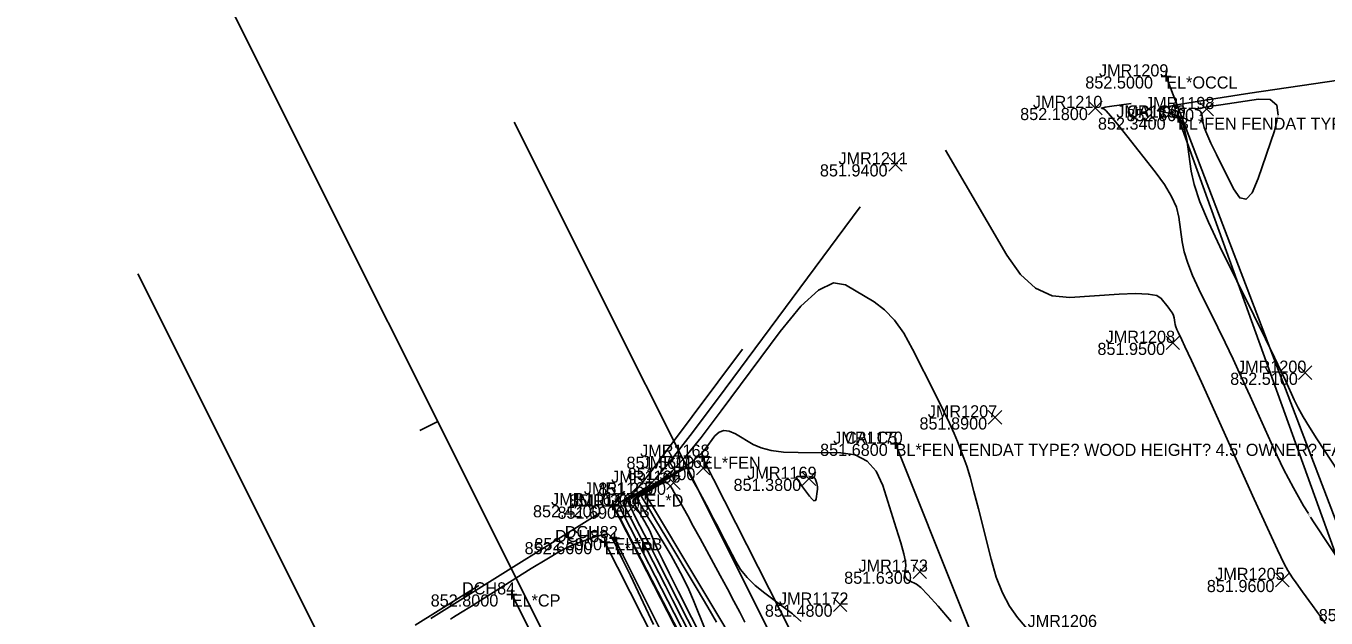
# Model space of a CAD drawing. Extents: x 1654928 to 1810050, y 486881 to 626330.
# Drawn here: x 1801297.5 to 1801426.1, y 489990.4 to 490049 of the extents above; entities that cross this region are included whole.
import ezdxf

# ---------------------------------------------------------------- set-up
doc = ezdxf.new("R2010")
doc.units = 0
for name, color, linetype in [('DR_X_Ditch', 7, 'Continuous'), ('DT_X_Contour_Major', 7, 'Continuous'), ('DT_X_Contour_Minor', 7, 'Continuous'), ('PV_X_EOP', 7, 'Continuous'), ('PV_X_Shoulder', 7, 'Continuous'), ('RD_X_Fence', 7, 'Continuous'), ('RW_X_Esmt_SH', 7, 'Continuous'), ('SV_X_Break_Lines', 7, 'Continuous'), ('SV_X_Center_of_Pavt', 7, 'Continuous'), ('SV_X_CL_Survey_20', 7, 'Continuous'), ('SV_X_Occupation_Line', 7, 'Continuous'), ('SV_X_Random_Point', 7, 'Continuous'), ('SV_X_Shot_Marker', 7, 'Continuous'), ('SV_X_Text_Comment', 7, 'Continuous'), ('SV_X_Text_Elevation', 7, 'Continuous'), ('SV_X_Text_Name', 7, 'Continuous')]:
    doc.layers.add(name, color=color, linetype=linetype)

msp = doc.modelspace()

# ---------------------------------------------------------------- linework, layer by layer
at = {"layer": 'DR_X_Ditch'}
msp.add_lwpolyline([(1801398.42, 489926.9), (1801390.07, 489943.2), (1801378.94, 489964.4), (1801369.21, 489985.15), (1801358.75, 490002.61)], dxfattribs=at)
at = {"layer": 'DT_X_Contour_Major'}
for points in [[(1801388.41, 490036.67), (1801394.48, 490026.3), (1801395.85, 490024.36), (1801397.34, 490023.02), (1801398.97, 490022.26), (1801400.73, 490022.09), (1801405.6, 490022.42), (1801407.23, 490022.48), (1801408.47, 490022.44), (1801409.31, 490022.28), (1801409.77, 490022), (1801410.46, 490021.13), (1801410.69, 490020.82), (1801410.87, 490020.54), (1801410.98, 490020.3), (1801411.03, 490020.1), (1801411.1, 490019.61), (1801411.14, 490019.41), (1801411.21, 490019.19), (1801411.31, 490018.94), (1801411.43, 490018.67), (1801411.81, 490017.91), (1801412.11, 490017.26), (1801412.75, 490015.86), (1801413.73, 490013.72), (1801418.97, 490002.14), (1801420.28, 489999.26), (1801421.27, 489997.12), (1801421.93, 489995.73), (1801422.28, 489995.08), (1801422.76, 489994.35), (1801423.1, 489993.86), (1801423.75, 489992.95), (1801424.73, 489991.61), (1801426.02, 489989.84)], [(1801379.98, 490031.06), (1801365.87, 490012.04), (1801363.16, 490008.43), (1801361.08, 490005.77), (1801359.64, 490004.05), (1801358.82, 490003.27), (1801357.49, 490002.46), (1801357.05, 490002.19), (1801356.75, 490001.98), (1801356.58, 490001.83), (1801356.54, 490001.74), (1801356.61, 490001.58), (1801356.71, 490001.38), (1801357.33, 490000.16), (1801360.06, 489994.86), (1801360.72, 489993.56), (1801361.43, 489992.17), (1801364.25, 489986.6)]]:
    msp.add_lwpolyline(points, dxfattribs=at)
at = {"layer": 'DT_X_Contour_Minor'}
for points in [[(1801442.36, 490045.83), (1801418.51, 490042.31), (1801414.11, 490041.64), (1801411.12, 490041.13), (1801409.55, 490040.78), (1801409.39, 490040.58), (1801410.86, 490040.29), (1801411.36, 490040.05), (1801411.76, 490039.54), (1801412.07, 490038.77), (1801412.28, 490037.73), (1801412.71, 490034.61), (1801413.01, 490033.27), (1801413.59, 490031.58), (1801414.43, 490029.54), (1801415.56, 490027.16), (1801418.92, 490020.35), (1801420.06, 490018.02), (1801420.96, 490016.16), (1801421.63, 490014.76), (1801422.07, 490013.83), (1801422.92, 490011.96), (1801423.3, 490011.19), (1801423.8, 490010.29), (1801424.42, 490009.26), (1801425.16, 490008.11), (1801427.3, 490004.85)], [(1801424.32, 490000.73), (1801423.84, 490001.48), (1801422.83, 490003.26), (1801421.86, 490005.11), (1801420.94, 490007.05), (1801418.55, 490012.33), (1801417.68, 490014.24), (1801416.86, 490016.01), (1801416.08, 490017.64), (1801415.36, 490019.13), (1801413.49, 490022.92), (1801412.87, 490024.27), (1801412.38, 490025.51), (1801412.04, 490026.62), (1801411.84, 490027.6), (1801411.5, 490030.06), (1801411.26, 490031.03), (1801410.78, 490032.11), (1801410.08, 490033.28), (1801409.15, 490034.55), (1801406.36, 490038.09), (1801405.43, 490039.25), (1801404.74, 490040.08), (1801404.3, 490040.59), (1801404.09, 490040.77), (1801403.87, 490040.82), (1801403.85, 490040.84), (1801403.97, 490040.88), (1801404.23, 490040.93), (1801404.63, 490040.99), (1801406.8, 490041.31)], [(1801415.23, 490036.25), (1801414.68, 490037.39), (1801414.27, 490038.29), (1801414.01, 490038.94), (1801413.9, 490039.33), (1801413.8, 490040.05), (1801413.76, 490040.29), (1801413.68, 490040.47), (1801413.59, 490040.59), (1801413.48, 490040.64), (1801413.14, 490040.71), (1801413.2, 490040.76), (1801413.64, 490040.85), (1801414.47, 490040.99), (1801415.67, 490041.17), (1801419.39, 490041.72), (1801420.53, 490041.68), (1801421.18, 490041.14), (1801421.32, 490040.14)], [(1801421.23, 490039.73), (1801420.97, 490038.58), (1801419.36, 490033.86), (1801418.76, 490032.46), (1801418.15, 490031.83), (1801417.53, 490031.96), (1801416.9, 490032.85), (1801415.23, 490036.25)], [(1801397.82, 489987.74), (1801395.56, 489990.43), (1801394.76, 489991.54), (1801394.06, 489992.88), (1801393.45, 489994.43), (1801392.93, 489996.19), (1801391.68, 490001.19), (1801391.24, 490002.91), (1801390.86, 490004.32), (1801390.53, 490005.41), (1801390.25, 490006.2), (1801389.6, 490007.86), (1801389.28, 490008.62), (1801388.81, 490009.65), (1801388.19, 490010.94), (1801387.42, 490012.49), (1801385.17, 490017), (1801384.3, 490018.56), (1801383.37, 490019.86), (1801382.39, 490020.89), (1801381.36, 490021.66), (1801378.54, 490023.35), (1801377.34, 490023.54), (1801375.86, 490022.83), (1801374.1, 490021.23), (1801372.06, 490018.73), (1801366.24, 490010.88), (1801364.24, 490008.25), (1801362.6, 490006.24), (1801361.32, 490004.86), (1801360.4, 490004.1), (1801358.43, 490002.91), (1801357.78, 490002.5), (1801357.34, 490002.19), (1801357.09, 490001.97), (1801357.03, 490001.83), (1801357.14, 490001.6), (1801357.2, 490001.47), (1801357.3, 490001.26), (1801357.45, 490000.97), (1801357.64, 490000.6), (1801358.2, 489999.5), (1801359.09, 489997.77), (1801359.88, 489996.21), (1801360.9, 489994.19), (1801363.93, 489988.21)], [(1801368.33, 490017), (1801360.94, 490007.04), (1801359.52, 490005.15), (1801358.43, 490003.75), (1801357.67, 490002.85), (1801357.25, 490002.45), (1801356.55, 490002.02), (1801356.32, 490001.88), (1801356.16, 490001.77), (1801356.07, 490001.69), (1801356.05, 490001.64), (1801356.09, 490001.56), (1801356.6, 490000.56), (1801361.59, 489990.85), (1801362.98, 489988.13)], [(1801389, 489990.02), (1801387.7, 489991.54), (1801386.69, 489992.67), (1801385.98, 489993.39), (1801385.57, 489993.72), (1801384.85, 489994.06), (1801384.62, 489994.2), (1801384.46, 489994.38), (1801384.39, 489994.59), (1801384.39, 489994.83), (1801384.49, 489995.54), (1801384.46, 489995.97), (1801384.3, 489996.73), (1801384, 489997.82), (1801383.56, 489999.25), (1801382.21, 490003.5), (1801381.57, 490004.9), (1801380.67, 490005.9), (1801379.5, 490006.51), (1801378.06, 490006.72), (1801373.86, 490006.74), (1801372.41, 490006.8), (1801371.18, 490006.96), (1801370.18, 490007.21), (1801369.41, 490007.55), (1801367.66, 490008.6), (1801367.04, 490008.88), (1801366.5, 490008.94), (1801366.02, 490008.78), (1801365.62, 490008.4), (1801364.65, 490007.09), (1801364.21, 490006.59), (1801363.62, 490006.06), (1801362.87, 490005.51), (1801361.97, 490004.93), (1801359.36, 490003.35), (1801358.51, 490002.82), (1801357.92, 490002.41), (1801357.58, 490002.14), (1801357.49, 490001.98), (1801357.6, 490001.74), (1801357.67, 490001.62), (1801357.77, 490001.43), (1801357.92, 490001.17), (1801358.12, 490000.85), (1801358.69, 489999.89), (1801358.89, 489999.54), (1801359.07, 489999.19), (1801359.24, 489998.85), (1801359.38, 489998.51), (1801359.73, 489997.63), (1801359.97, 489997.09), (1801360.42, 489996.15), (1801361.09, 489994.8), (1801361.98, 489993.04), (1801364.62, 489987.82)], [(1801364.64, 489989.25), (1801363.51, 489992.11), (1801363.05, 489993.19), (1801362.52, 489994.29), (1801361.93, 489995.42), (1801361.28, 489996.56), (1801359.43, 489999.62), (1801358.83, 490000.63), (1801358.39, 490001.38), (1801358.11, 490001.84), (1801358, 490002.04), (1801357.93, 490002.2), (1801357.99, 490002.3), (1801358.25, 490002.51), (1801358.69, 490002.8), (1801359.31, 490003.19), (1801361.24, 490004.36), (1801361.88, 490004.74), (1801362.34, 490005), (1801362.64, 490005.15), (1801362.77, 490005.19), (1801362.89, 490005.13), (1801362.93, 490005.1), (1801362.96, 490005.06), (1801362.99, 490005), (1801363.02, 490004.93), (1801363.08, 490004.72), (1801363.15, 490004.56), (1801363.31, 490004.24), (1801363.57, 490003.75), (1801363.92, 490003.11), (1801364.97, 490001.17), (1801365.36, 490000.43), (1801365.76, 489999.67), (1801366.17, 489998.9), (1801366.58, 489998.11), (1801367.67, 489995.97), (1801368.16, 489995.17), (1801368.8, 489994.38), (1801369.6, 489993.6), (1801370.55, 489992.82), (1801373.29, 489990.77), (1801374.14, 489990.04)], [(1801374.56, 490004.38), (1801374.27, 490004.39), (1801374.04, 490004.38), (1801373.87, 490004.38), (1801373.76, 490004.37), (1801373.71, 490004.36), (1801373.65, 490004.31), (1801373.67, 490004.25), (1801373.77, 490004.09), (1801373.94, 490003.84), (1801374.19, 490003.49), (1801374.96, 490002.44)], [(1801374.96, 490002.44), (1801375.22, 490002.13), (1801375.41, 490001.98), (1801375.55, 490002), (1801375.62, 490002.18), (1801375.72, 490002.88), (1801375.75, 490003.13), (1801375.76, 490003.35), (1801375.74, 490003.54), (1801375.71, 490003.7), (1801375.58, 490004.09), (1801375.51, 490004.21), (1801375.38, 490004.31), (1801375.2, 490004.36), (1801374.98, 490004.38)], [(1801356.68, 490002.94), (1801356.01, 490002.04), (1801355.88, 490001.86), (1801355.78, 490001.74), (1801355.71, 490001.66), (1801355.67, 490001.62), (1801355.61, 490001.58), (1801355.59, 490001.57), (1801355.56, 490001.55), (1801355.56, 490001.55), (1801356.25, 490000.21), (1801363.12, 489986.85)], [(1801365.76, 489989.95), (1801364.92, 489991.43), (1801363.87, 489993.22), (1801360.75, 489998.4), (1801359.73, 490000.1), (1801359, 490001.33), (1801358.55, 490002.07), (1801358.39, 490002.34), (1801358.36, 490002.41), (1801358.39, 490002.46), (1801358.51, 490002.56), (1801358.72, 490002.7), (1801359.02, 490002.88), (1801359.93, 490003.44), (1801360.24, 490003.61), (1801360.48, 490003.73), (1801360.66, 490003.78), (1801360.77, 490003.78), (1801360.97, 490003.68), (1801361.07, 490003.59), (1801361.21, 490003.42), (1801361.38, 490003.16), (1801361.59, 490002.81), (1801362.21, 490001.76), (1801362.51, 490001.24), (1801362.93, 490000.48), (1801363.48, 489999.48), (1801364.16, 489998.23), (1801366.14, 489994.58), (1801366.85, 489993.26), (1801367.49, 489992.05), (1801368.07, 489990.96), (1801368.58, 489989.96)], [(1801354.31, 490000.81), (1801340.16, 489991.98), (1801337.52, 489990.31)], [(1801464.87, 489979.65), (1801443.27, 489983.53), (1801439.2, 489984.3), (1801436.26, 489984.97), (1801434.45, 489985.51), (1801433.76, 489985.95), (1801433.43, 489986.96), (1801433.26, 489987.37), (1801433, 489987.85), (1801432.65, 489988.41), (1801432.21, 489989.03), (1801430.92, 489990.79), (1801430.36, 489991.57), (1801429.65, 489992.6), (1801428.8, 489993.88), (1801427.79, 489995.4), (1801424.9, 489999.8), (1801424.54, 490000.37)], [(1801339.45, 489990.26), (1801339.76, 489990.45), (1801340.46, 489990.88), (1801341.54, 489991.56), (1801347.45, 489995.27), (1801348.98, 489996.21), (1801350.26, 489996.94), (1801351.27, 489997.47), (1801352.02, 489997.79), (1801353.68, 489998.37), (1801354.23, 489998.55), (1801354.66, 489998.65), (1801354.95, 489998.68), (1801355.11, 489998.63), (1801355.35, 489998.4), (1801355.54, 489998.09), (1801355.92, 489997.35), (1801356.49, 489996.18), (1801357.26, 489994.58), (1801359.54, 489989.72)], [(1801342.25, 489993.6), (1801335.96, 489989.67)]]:
    msp.add_lwpolyline(points, dxfattribs=at)
at = {"layer": 'PV_X_EOP'}
msp.add_lwpolyline([(1801533.68, 489642.19), (1801522.48, 489664.51), (1801511.88, 489685.34), (1801500.3, 489708.68), (1801491.1, 489726.66), (1801480.83, 489747.38), (1801466.88, 489774.66), (1801456.51, 489795.71), (1801444.64, 489819.01), (1801433.26, 489841.44), (1801422.03, 489864), (1801410.91, 489885.93), (1801399.82, 489908.09), (1801388.58, 489930.66), (1801376.23, 489955.19), (1801366.01, 489975.62), (1801354.72, 489997.89)], dxfattribs=at)
at = {"layer": 'PV_X_Shoulder'}
msp.add_lwpolyline([(1801534.47, 489642.46), (1801522.96, 489664.95), (1801512.6, 489685.48), (1801500.97, 489709.11), (1801491.77, 489727.02), (1801481.53, 489747.77), (1801467.48, 489775.07), (1801457.12, 489796.09), (1801445.57, 489819.4), (1801434.03, 489841.93), (1801422.68, 489864.34), (1801411.89, 489886.25), (1801400.66, 489908.45), (1801366.7, 489976.23), (1801355.68, 489998.28)], dxfattribs=at)
at = {"layer": 'RD_X_Fence'}
msp.add_line((1801411.43, 490039.91), (1801432.79, 489980.61), dxfattribs=at)
for points in [[(1801383.49, 490007.62), (1801396.54, 489974.9), (1801434.52, 489980.34), (1801464.87, 489979.65), (1801533.18, 489980.29)], [(1801406.8, 489921.92), (1801396.01, 489944.4), (1801383.89, 489967.43), (1801374.31, 489986.71), (1801364.34, 490006.34)]]:
    msp.add_lwpolyline(points, dxfattribs=at)
at = {"layer": 'RW_X_Esmt_SH'}
for p, q in [((1801569.15, 489592.81), (1801345.76, 490039.45)), ((1801533.56, 489574.54), (1801308.54, 490024.45))]:
    msp.add_line(p, q, dxfattribs=at)
at = {"layer": 'SV_X_Break_Lines'}
msp.add_lwpolyline([(1801445.79, 489822.14), (1801441.19, 489830.46), (1801435.21, 489842.68), (1801424.27, 489864.66), (1801412.81, 489886.98), (1801408.71, 489897.16), (1801400, 489913.18), (1801395.19, 489923.67), (1801385.65, 489941.64), (1801375, 489962.91), (1801364.94, 489983.14), (1801355.51, 490001.54)], dxfattribs=at)
at = {"layer": 'SV_X_Center_of_Pavt'}
msp.add_lwpolyline([(1801523.58, 489638.31), (1801512.85, 489659.48), (1801502.37, 489680.41), (1801490.82, 489703.95), (1801481.43, 489721.68), (1801470.8, 489742.83), (1801457.33, 489769.61), (1801446.39, 489792.46), (1801435.31, 489813.79), (1801423.54, 489836.52), (1801412.23, 489859.3), (1801401.2, 489881.35), (1801390, 489903.67), (1801378.78, 489926.72), (1801366.67, 489950.37), (1801356.57, 489970.63), (1801345.52, 489992.71)], dxfattribs=at)
at = {"layer": 'SV_X_CL_Survey_20'}
for p, q in [((1802886.98, 486913.25), (1801128.54, 490429.05)), ((1802886.98, 486913.25), (1801128.54, 490429.05)), ((1801338.21, 490009.83), (1801336.42, 490008.94))]:
    msp.add_line(p, q, dxfattribs=at)
at = {"layer": 'SV_X_Occupation_Line'}
msp.add_lwpolyline([(1801533.37, 489981.02), (1801493.84, 489980.7), (1801459.35, 489980.47), (1801434.37, 489980.75), (1801410.26, 490043.98)], dxfattribs=at)
at = {"layer": 'SV_X_Random_Point'}
for p, q in [((1801402.57, 490040.19), (1801403.91, 490041.52)), ((1801402.57, 490041.52), (1801403.91, 490040.19)), ((1801413.59, 490040.08), (1801414.93, 490041.41)), ((1801413.59, 490041.41), (1801414.93, 490040.08)), ((1801382.81, 490034.61), (1801384.14, 490035.95)), ((1801382.81, 490035.95), (1801384.14, 490034.61)), ((1801410.25, 490016.94), (1801411.58, 490018.28)), ((1801410.25, 490018.28), (1801411.58, 490016.94)), ((1801423.34, 490013.99), (1801424.67, 490015.32)), ((1801423.34, 490015.32), (1801424.67, 490013.99)), ((1801392.65, 490009.56), (1801393.98, 490010.9)), ((1801392.65, 490010.9), (1801393.98, 490009.56)), ((1801363.78, 490004.55), (1801365.11, 490005.89)), ((1801363.78, 490005.89), (1801365.11, 490004.55)), ((1801360.86, 490003.1), (1801362.19, 490004.43)), ((1801360.86, 490004.43), (1801362.19, 490003.1)), ((1801374.26, 490003.48), (1801375.59, 490004.81)), ((1801374.26, 490004.81), (1801375.59, 490003.48)), ((1801356.86, 490000.73), (1801358.19, 490002.06)), ((1801356.86, 490002.06), (1801358.19, 490000.73)), ((1801385.22, 489994.29), (1801386.55, 489995.63)), ((1801385.22, 489995.63), (1801386.55, 489994.29)), ((1801421.08, 489993.47), (1801422.42, 489994.81)), ((1801421.08, 489994.81), (1801422.42, 489993.47)), ((1801377.34, 489991.03), (1801378.68, 489992.36)), ((1801377.34, 489992.36), (1801378.68, 489991.03))]:
    msp.add_line(p, q, dxfattribs=at)
at = {"layer": 'SV_X_Shot_Marker'}
for p, q in [((1801409.76, 490043.98), (1801410.76, 490043.98)), ((1801410.26, 490044.48), (1801410.26, 490043.48)), ((1801410.26, 490043.98), (1801410.26, 490043.98)), ((1801410.93, 490039.91), (1801411.93, 490039.91)), ((1801410.93, 490039.91), (1801411.93, 490039.91)), ((1801411.43, 490040.41), (1801411.43, 490039.41)), ((1801411.43, 490040.41), (1801411.43, 490039.41)), ((1801411.43, 490039.91), (1801411.43, 490039.91)), ((1801411.43, 490039.91), (1801411.43, 490039.91)), ((1801383.49, 490008.12), (1801383.49, 490007.12)), ((1801383.49, 490008.12), (1801383.49, 490007.12)), ((1801364.34, 490006.84), (1801364.34, 490005.84)), ((1801382.99, 490007.62), (1801383.99, 490007.62)), ((1801382.99, 490007.62), (1801383.99, 490007.62)), ((1801383.49, 490007.62), (1801383.49, 490007.62)), ((1801383.49, 490007.62), (1801383.49, 490007.62)), ((1801363.84, 490006.34), (1801364.84, 490006.34)), ((1801364.34, 490006.34), (1801364.34, 490006.34)), ((1801358.25, 490002.61), (1801359.25, 490002.61)), ((1801358.75, 490003.11), (1801358.75, 490002.11)), ((1801358.75, 490002.61), (1801358.75, 490002.61)), ((1801355.01, 490001.54), (1801356.01, 490001.54)), ((1801355.51, 490002.04), (1801355.51, 490001.04)), ((1801355.51, 490001.54), (1801355.51, 490001.54)), ((1801355.68, 489998.78), (1801355.68, 489997.78)), ((1801354.22, 489997.89), (1801355.22, 489997.89)), ((1801354.72, 489998.39), (1801354.72, 489997.39)), ((1801354.72, 489997.89), (1801354.72, 489997.89)), ((1801355.18, 489998.28), (1801356.18, 489998.28)), ((1801355.68, 489998.28), (1801355.68, 489998.28)), ((1801345.02, 489992.71), (1801346.02, 489992.71)), ((1801345.52, 489993.21), (1801345.52, 489992.21)), ((1801345.52, 489992.71), (1801345.52, 489992.71))]:
    msp.add_line(p, q, dxfattribs=at)

# ---------------------------------------------------------------- texts
at = {"layer": 'DT_X_Contour_Minor'}
for s, rotation, p in [('853', 78.3865, (1801421.32, 490039.76)), ('851', 359.4979, (1801374.64, 490004.31)), ('852', 302.098, (1801424.28, 490000.65))]:
    msp.add_text(s, height=0.14, rotation=rotation, dxfattribs=at).set_placement(p)
at = {"layer": 'SV_X_Text_Comment'}
for s, p in [('EL*OCCL', (1801410.26, 490042.78)), ("BL*FEN FENDAT TYPE? WOOD HEIGHT? 4.5' OWNER? FARMER ELECTRIC", (1801411.43, 490038.71)), ("BL*FEN FENDAT TYPE? WOOD HEIGHT? 4.5' OWNER? FARMER ELECTRIC", (1801383.49, 490006.42)), ('EL*FEN', (1801364.34, 490005.14)), ('EL*D', (1801358.75, 490001.41)), ('EL*B', (1801355.51, 490000.34)), ('EL*EP', (1801354.72, 489996.69)), ('EL*EB', (1801355.68, 489997.08)), ('EL*CP', (1801345.52, 489991.51))]:
    msp.add_text(s, height=1.2, dxfattribs=at).set_placement(p)
at = {"layer": 'SV_X_Text_Elevation'}
for s, p in [('852.5000', (1801402.25, 490042.78)), ('852.1800', (1801395.81, 490039.66)), ('852.3400', (1801403.5, 490038.71)), ('852.3400', (1801403.5, 490038.71)), ('852.6600', (1801406.32, 490039.55)), ('851.9400', (1801376, 490034.08)), ('851.9500', (1801403.45, 490016.41)), ('852.5100', (1801416.58, 490013.45)), ('851.8900', (1801385.85, 490009.03)), ('851.6800', (1801376.02, 490006.42)), ('851.6800', (1801376.02, 490006.42)), ('851.5600', (1801356.87, 490005.14)), ('851.5400', (1801356.99, 490004.02)), ('851.3800', (1801367.46, 490002.95)), ('851.0200', (1801351.21, 490001.41)), ('851.2300', (1801354.08, 490002.57)), ('852.4200', (1801347.62, 490000.34)), ('851.6900', (1801350.04, 490000.2)), ('852.6600', (1801346.79, 489996.69)), ('852.5900', (1801347.76, 489997.08)), ('851.6300', (1801378.4, 489993.76)), ('851.9600', (1801414.27, 489992.94)), ('852.8000', (1801337.5, 489991.51)), ('851.4800', (1801370.56, 489990.5)), ('852.3000', (1801425.34, 489990.06))]:
    msp.add_text(s, height=1.2, dxfattribs=at).set_placement(p)
at = {"layer": 'SV_X_Text_Name'}
for s, p in [('JMR1209', (1801403.6, 490043.98)), ('JMR1210', (1801397.07, 490040.86)), ('JMR1199', (1801405.32, 490039.91)), ('CALC6', (1801406.35, 490039.91)), ('JMR1198', (1801408.15, 490040.75)), ('JMR1211', (1801377.84, 490035.28)), ('JMR1208', (1801404.26, 490017.61)), ('JMR1200', (1801417.25, 490014.65)), ('JMR1207', (1801386.67, 490010.23)), ('JMR1170', (1801377.32, 490007.62)), ('CALC5', (1801378.49, 490007.62)), ('JMR1168', (1801358.22, 490006.34)), ('JMR1167', (1801358.35, 490005.22)), ('JMR1169', (1801368.81, 490004.15)), ('JMR1166', (1801355.35, 490003.77)), ('JMR1163', (1801349.41, 490001.54)), ('JMR1164', (1801351.43, 490001.4)), ('JMR1165', (1801352.65, 490002.61)), ('DCH83', (1801349.8, 489997.89)), ('DCH82', (1801350.76, 489998.28)), ('JMR1173', (1801379.82, 489994.96)), ('JMR1205', (1801415.1, 489994.14)), ('DCH84', (1801340.6, 489992.71)), ('JMR1172', (1801371.95, 489991.7)), ('JMR1206', (1801396.54, 489989.48))]:
    msp.add_text(s, height=1.2, dxfattribs=at).set_placement(p)

doc.saveas('drawing.dxf')
